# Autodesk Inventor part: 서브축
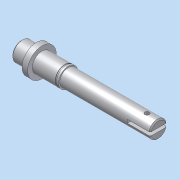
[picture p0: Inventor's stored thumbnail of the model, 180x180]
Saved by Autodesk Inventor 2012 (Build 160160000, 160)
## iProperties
Company: 한국ATC센터
Created: 2014-12
Part Number: 서브축
Document SubType Name: Modeling
Designer: KYOUNG IL JANG
Density: 1 g/cm^3
Mass: 23.2871 g
Surface Area: 76.512 cm^2
Volume: 23.2871 cm^3
Material: 기본값
Author: KYOUNG IL JANG
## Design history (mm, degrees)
sketch "스케치1"
  geometry: L1 (0, 0)-(120, 0); L2 (0, 0)-(0, 7.5); L3 (1, 8.5)-(13, 8.5); L4 (13, 8.5)-(13, 12.5); L5 (13, 12.5)-(18, 12.5); L6 (18, 12.5)-(18, 8.5); L7 (18, 8.5)-(41, 8.5); L8 (120, 7.5)-(120, 0); L9 (0, 7.5)-(1, 8.5); L10 (41, 8.5)-(41, 7.5); L11 (41, 7.5)-(120, 7.5); 1 further point
  constraints: 22 end point, 3 parallel, 3 perpendicular, 2 collinear, 2 point on line, 2 vertical, 1 horizontal
  dimensions: "d0" = 5 distance of L4.end L5.end; "d1" = 17 diameter of L7 L1; "d2" = 13 distance of point (0, 8.5) L3.end; "d3" = 25 diameter of L5 L1; "d4" = 120 distance of L1.start L1.end; "d5" = 1 distance of L2.end point (0, 8.5); "d6" = 1 distance of L3.start point (0, 8.5) (= d5); "d15" = 15 diameter of L11 L1; "d16" = 23 distance of L6.end L7.end
revolve "회전1" sketch "스케치1" stored, may be unused: angle "d9" = 90 deg
node "작업 평면1"
sketch "스케치2"
  geometry: L1 (11.5, 12.5)-(11.5, -12.5) reference; L2 (-3, 2.5)-(6, 2.5); L3 (6, -2.5)-(-3, -2.5); A1 r 2.5 centre (6, 0) between (6, -2.5) and (6, 2.5); A2 r 2.5 centre (-3, 0) between (-3, 2.5) and (-3, -2.5); 1 further point
  constraints: 4 end point, 4 point on circle, 4 tangent, 2 centre point, 1 horizontal alignment, 1 parallel, 1 perpendicular
  dimensions: "d10" = 5 distance between parallel lines of L3 L2; "d11" = 14 dimension on A1 A2; "d12" = 3 distance edge to line of A1 L1
extrude "돌출1" cut sketch "스케치2" distance "d13" = 3; taper "d14" = 0 deg
sketch "스케치3"
  geometry: L1 (18, -12.5)-(18, 12.5) reference; L2 (13, -12.5)-(13, 12.5) reference; L3 (18, 8.5)-(41, 8.5) reference; L4 (38, 8.5)-(39.15, 8.5); L5 (39.15, 8.5)-(39.15, 8.1); L6 (39.15, 8.1)-(38, 8.1); L7 (38, 8.1)-(38, 8.5); L8 (-24, 0)-(144, 0) reference; 1 further point
  constraints: 8 end point, 2 parallel, 1 horizontal, 1 perpendicular, 1 point on line
  dimensions: "d17" = 20 distance between parallel lines of L7 L1; "d18" = 1.15 distance of L5.end L6.end; "d19" = 8.1 distance between parallel lines of L6 L8
revolve "회전2" sketch "스케치3" stored, may be unused: angle "d20" = 90 deg
chamfer "모따기1" distance "d21" = 1; stored, may be unused: second distance "d22" = 2, angle "d23" = 45 deg
sketch "스케치4"
  geometry: L1 (-120, 1.5)-(-100, 1.5); L2 (-100, 1.5)-(-100, -1.5); L3 (-100, -1.5)-(-120, -1.5); L4 (-120, -1.5)-(-120, 1.5); L5 (-120, -6.5)-(-120, 6.5) reference; 2 further points
  constraints: 8 end point, 2 parallel, 1 collinear, 1 horizontal, 1 horizontal alignment, 1 midpoint, 1 perpendicular
  dimensions: "d24" = 3 distance between parallel lines of L3 L1; "d25" = 20 distance of L2.end L3.end
extrude "돌출2" cut sketch "스케치4" stored distance "d26" = 10; taper "d27" = 0 deg
sketch "스케치5"
  geometry: L1 (120, 6.325)-(120, -6.325) reference; C1 r 2 at (110, 0); 1 further point
  constraints: 1 centre point, 1 horizontal alignment
  dimensions: "d28" = 4 diameter of C1; "d29" = 10 distance from line of L1 C1.centre
extrude "돌출3" cut sketch "스케치5" stored distance "d30" = 10; taper "d31" = 0 deg
node "솔리드1"
node "투영된 루프1"
